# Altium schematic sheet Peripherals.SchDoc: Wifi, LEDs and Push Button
size A4; Author: N.P; CompanyName: STMicroelectronics; Organization: MCD/APPLIS/LMS; DocumentNumber: MB1260; SheetNumber: 11; SheetTotal: 13; Project: STM32F723e-DISCO
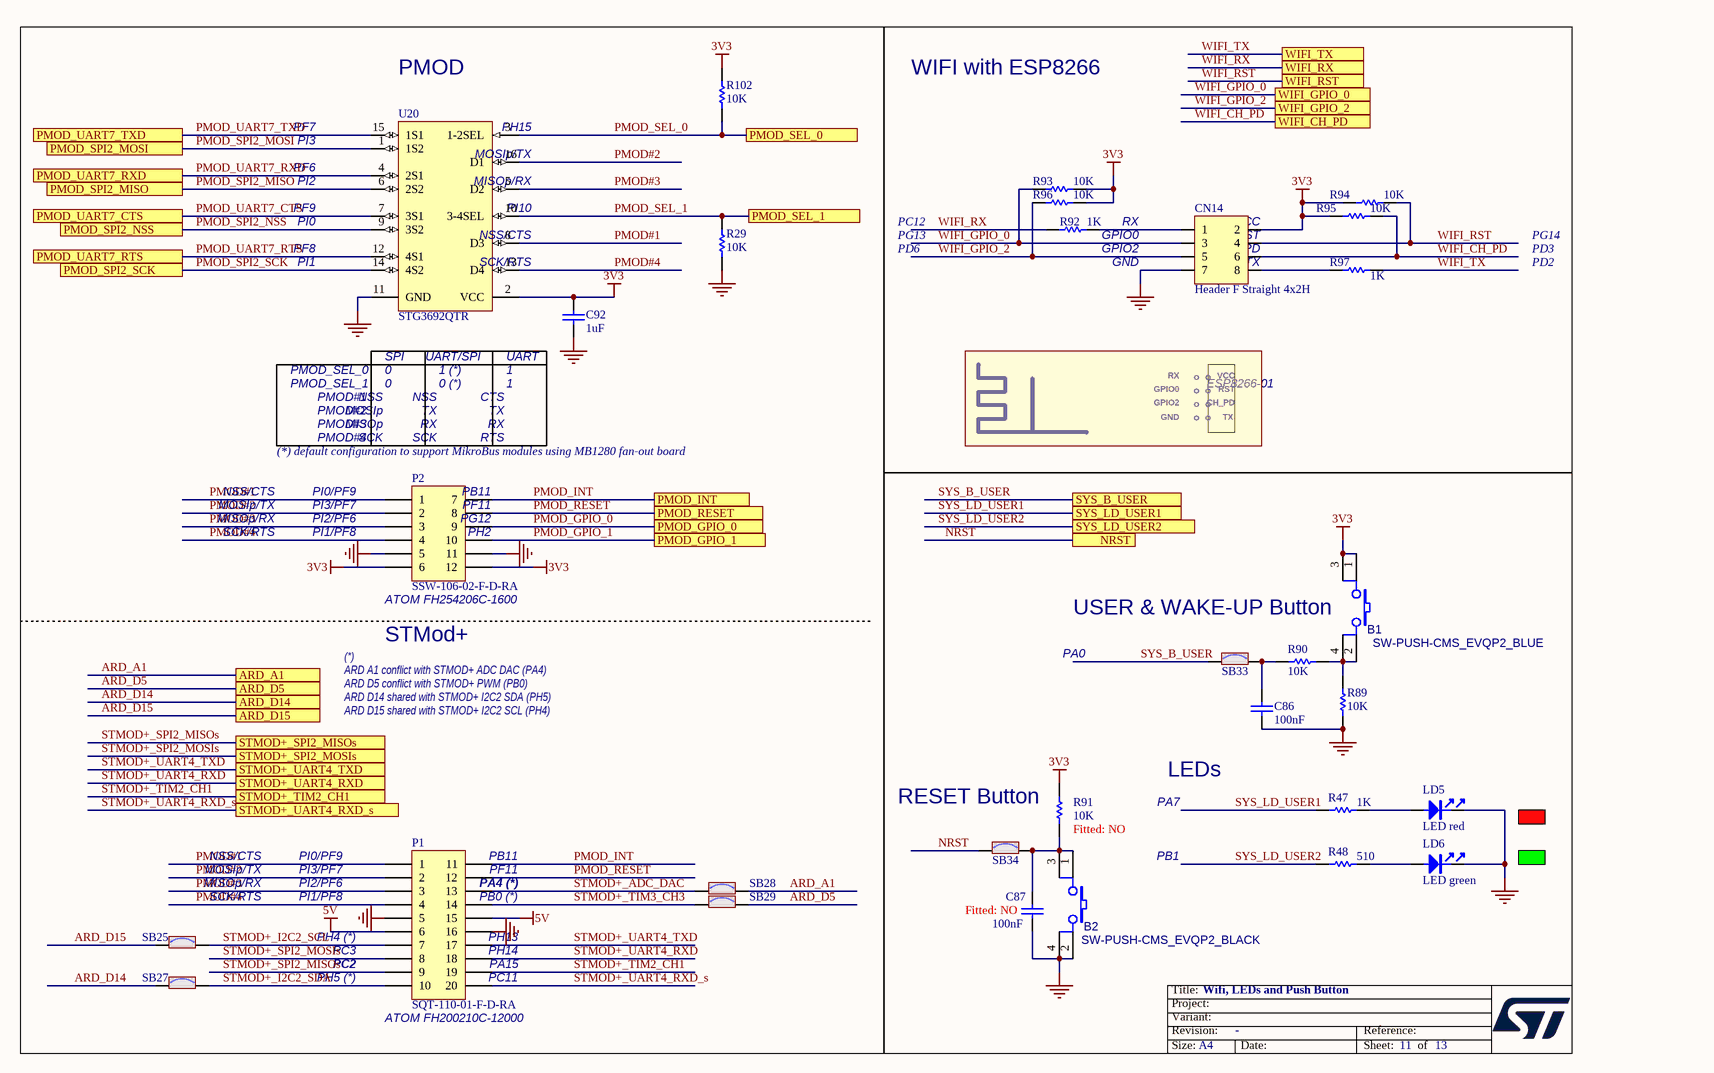
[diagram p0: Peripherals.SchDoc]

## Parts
B1  SW-PUSH-CMS_EVQP2_BLUE  [TACT_4SM_3R5X5R5]
B2  SW-PUSH-CMS_EVQP2_BLACK  [TACT_4SM_3R5X5R5]
C86  100nF  [0402C]
C87  100nF  Fitted: NO  [0402C]
C92  1uF  [0603C]
CN14  Header F Straight 4x2H  [HDR_2X4_2R54]
LD5  LED red  [0603D]
LD6  LED green  [0603D]
P1  SQT-110-01-F-D-RA  [SQT-110-01-F-D-RA]
P2  SSW-106-02-F-D-RA  [SSW-106-02-F-D-RA]
R29  10K  [0402R]
R47  value 1K  [0603R]  (hidden comment: 1K_1%_0603)
R48  value 510  [0603R]  (hidden comment: 510_1%_0603)
R89  10K  [0402R]
R90  10K  [0402R]
R91  Fitted: NO  [0402R]  (hidden comment: 10K)
R92  1K  [0402R]
R93  10K  [0402R]
R94  10K  [0402R]
R95  10K  [0402R]
R96  10K  [0402R]
R97  1K  [0402R]
R102  10K  [0402R]
SB25  Solder Bridge ON  [JP2_SMD]  (value not drawn)
SB27  Solder Bridge ON  [JP2_SMD]  (value not drawn)
SB28  Solder Bridge ON  [JP2_SMD]  (value not drawn)
SB29  Solder Bridge ON  [JP2_SMD]  (value not drawn)
SB33  Solder Bridge ON  [JP2_SMD]  (value not drawn)
SB34  Solder Bridge ON  [JP2_SMD]  (value not drawn)
U20  STG3692QTR  [QFN16_0R4_2R5X1R7]

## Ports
ARD_A1, ARD_D5, ARD_D14, ARD_D15, NRST, PMOD_GPIO_0, PMOD_GPIO_1, PMOD_INT, PMOD_RESET, PMOD_SEL_0, PMOD_SEL_1, PMOD_SPI2_MISO, PMOD_SPI2_MOSI, PMOD_SPI2_NSS, PMOD_SPI2_SCK, PMOD_UART7_CTS, PMOD_UART7_RTS, PMOD_UART7_RXD, PMOD_UART7_TXD, STMOD+_SPI2_MISOs, STMOD+_SPI2_MOSIs, STMOD+_TIM2_CH1, STMOD+_UART4_RXD, STMOD+_UART4_RXD_s, STMOD+_UART4_TXD, SYS_B_USER, SYS_LD_USER1, SYS_LD_USER2, WIFI_CH_PD, WIFI_GPIO_0, WIFI_GPIO_2, WIFI_RST, WIFI_RX, WIFI_TX

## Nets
3V3: B1.1 B1.3 C92.1 CN14.2 P2.6 P2.12 R91.2 R93.1 R94.1 R95.1 R96.1 R102.2 U20.2(VCC)
5V: P1.6 P1.15
GND: B2.2 B2.4 C86.1 C87.1 C92.2 CN14.7 LD5.2 LD6.2 P1.5 P1.16 P2.5 P2.11 R29.1 R89.1 U20.11(GND)
ARD_A1: SB28.2 ; port ARD_A1
ARD_D5: SB29.2 ; port ARD_D5
ARD_D14: SB27.1 ; port ARD_D14
ARD_D15: SB25.1 ; port ARD_D15
NRST: SB34.1 ; port NRST
PMOD#1: P1.1 P2.1 U20.8(D3)
PMOD#2: P1.2 P2.2 U20.16(D1)
PMOD#3: P1.3 P2.3 U20.5(D2)
PMOD#4: P1.4 P2.4 U20.13(D4)
PMOD_GPIO_0: P2.9 ; port PMOD_GPIO_0
PMOD_GPIO_1: P2.10 ; port PMOD_GPIO_1
PMOD_INT: P1.11 P2.7 ; port PMOD_INT
PMOD_RESET: P1.12 P2.8 ; port PMOD_RESET
PMOD_SEL_0: R102.1 U20.3(1-2SEL) ; port PMOD_SEL_0
PMOD_SEL_1: R29.2 U20.10(3-4SEL) ; port PMOD_SEL_1
PMOD_SPI2_MISO: U20.6(2S2) ; port PMOD_SPI2_MISO
PMOD_SPI2_MOSI: U20.1(1S2) ; port PMOD_SPI2_MOSI
PMOD_SPI2_NSS: U20.9(3S2) ; port PMOD_SPI2_NSS
PMOD_SPI2_SCK: U20.14(4S2) ; port PMOD_SPI2_SCK
PMOD_UART7_CTS: U20.7(3S1) ; port PMOD_UART7_CTS
PMOD_UART7_RTS: U20.12(4S1) ; port PMOD_UART7_RTS
PMOD_UART7_RXD: U20.4(2S1) ; port PMOD_UART7_RXD
PMOD_UART7_TXD: U20.15(1S1) ; port PMOD_UART7_TXD
STMOD+_ADC_DAC: P1.13 SB28.1
STMOD+_I2C2_SCL: P1.7 SB25.2
STMOD+_I2C2_SDA: P1.10 SB27.2
STMOD+_SPI2_MISOs: P1.9 ; port STMOD+_SPI2_MISOs
STMOD+_SPI2_MOSIs: P1.8 ; port STMOD+_SPI2_MOSIs
STMOD+_TIM2_CH1: P1.19 ; port STMOD+_TIM2_CH1
STMOD+_TIM3_CH3: P1.14 SB29.1
STMOD+_UART4_RXD: P1.18 ; port STMOD+_UART4_RXD
STMOD+_UART4_RXD_s: P1.20 ; port STMOD+_UART4_RXD_s
STMOD+_UART4_TXD: P1.17 ; port STMOD+_UART4_TXD
SYS_B_USER: SB33.1 ; port SYS_B_USER
SYS_LD_USER1: R47.1 ; port SYS_LD_USER1
SYS_LD_USER2: R48.1 ; port SYS_LD_USER2
WIFI_CH_PD: CN14.6 R95.2 ; port WIFI_CH_PD
WIFI_GPIO_0: CN14.3 R93.2 ; port WIFI_GPIO_0
WIFI_GPIO_2: CN14.5 R96.2 ; port WIFI_GPIO_2
WIFI_RST: CN14.4 R94.2 ; port WIFI_RST
WIFI_RX: R92.1 ; port WIFI_RX
WIFI_TX: R97.2 ; port WIFI_TX
NetB1_2: B1.2 B1.4 R89.2 R90.2
NetB2_1: B2.1 B2.3 C87.2 R91.1 SB34.2
NetC86_2: C86.2 R90.1 SB33.2
NetCN14_1: CN14.1 R92.2
NetCN14_8: CN14.8 R97.1
NetLD5_1: LD5.1 R47.2
NetLD6_1: LD6.1 R48.2

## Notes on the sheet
- PF7
- PMOD
- (near U20) PH15
- WIFI with ESP8266
- PI3
- PF6
- PI2
- (near U20) MOSIp/TX
- (near U20) MISOp/RX
- PF9
- PI1
- PI0
- PF8
- (near U20) PI10
- (near U20) NSS/CTS
- SCK/RTS
- PC12
- PG13
- PD6
- (near CN14) GND
- (near CN14) GPIO2
- (near CN14) GPIO0
- RX
- (near CN14) VCC
- (near CN14) CH_PD
- (near CN14) RST
- (near CN14) TX
- PG14
- PD3
- PD2
- PMOD_SEL_0
- PMOD_SEL_1
- PMOD#1
- 0
- NSS
- SPI
- UART/SPI
- 0 (*)
- 1 (*)
- CTS
- UART
- 1
- GPIO2
- GPIO0
- ° °
- VCC
- CH_PD
- RST
- ESP8266-01
- (near P2) (*) default configuration to support MikroBus modules using MB1280 fan-out board
- PMOD#2
- PMOD#3
- PMOD#4
- MOSIp
- MISOp
- SCK
- TX
- RTS
- GND
- NSS/CTS
- MOSIp/TX
- MISOp/RX
- (near P2) PI0/PF9
- (near P2) PI3/PF7
- (near P2) PI2/PF6
- (near P2) PI1/PF8
- (near P2) PB11
- (near P2) PF11
- (near P2) PG12
- (near P2) PH2
- (near P2) ATOM FH254206C-1600
- STMod+
- USER & WAKE-UP Button
- PA0
- (*)
  ARD A1 conflict with STMOD+ ADC DAC (PA4)
  ARD D5 conflict with STMOD+ PWM (PB0)
  ARD D14 shared with STMOD+ I2C2 SDA (PH5)
  ARD D15 shared with STMOD+ I2C2 SCL (PH4)
- RESET Button
- LEDs
- PA7
- (near P1) PI0/PF9
- (near P1) PI3/PF7
- PB11
- PF11
- PB1
- (near P1) PI2/PF6
- (near P1) PI1/PF8
- (near P1) PH4 (*)
- PA4 (*)
- PB0 (*)
- PH13
- (near P1) PC3
- (near P1) PC2
- (near P1) PH5 (*)
- PH14
- PA15
- PC11
- (near P1) ATOM FH200210C-12000

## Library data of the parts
B1 = SW-PUSH-CMS_EVQP2_BLUE: EVQP2 - 4.7mm x 3.5 mm SMD Light Touch Switch; Manuf_2: Panasonic; Manuf_Part_2: EVQP2B02B; Manuf_Part_1: C-TS-02H-2.5-B-V-T/R; Manuf_1: Jiubaba; Ordered by: Subcon; Fitted: YES
B2 = SW-PUSH-CMS_EVQP2_BLACK: EVQP2 - 4.7mm x 3.5 mm SMD Light Touch Switch; Manuf_2: Panasonic; Manuf_Part_2: EVQP2F02K; Manuf_1: Jiubaba; Manuf_Part_1: C-TS-02H-2.5-K-V-T/R; Ordered by: Subcon; Fitted: YES
C86 = Cap_100nF_X7R_10%_0402: Capacitor,100nF,16V,X7R,10%,0402,YAGEO; Manuf_Part_1: CC0402KRX7R7BB104; Ordered by: Subcon; Fitted: YES
C87 = Cap_100nF_X7R_10%_0402: Capacitor,100nF,16V,X7R,10%,0402,YAGEO; Manuf_Part_1: CC0402KRX7R7BB104; Ordered by: Subcon
C92 = Cap_1uF_X5R_10%_0603: Capacitor,1uF,16V,X5R,10%,0603,YAGEO; Manuf_Part_1: CC0603KRX5R7BB105; Ordered by: Subcon; Fitted: YES
CN14 = Header 4X2F: Header Female, 4-Pin, Dual row, Straight; Manuf_Part_1: BL 2-8G; Manuf_1: Fischer Electronik; Fitted: YES; Ordered by: Subcon
LD5 = LED_red: LED red 0603; Manuf_1: everlight; Manuf_Part_1: 19-213-R6C-AP1Q2B/3T; Ordered by: Subcon; Fitted: YES
LD6 = LED_green: LED green 0603; Manuf_1: everlight; Manuf_Part_1: 19-213SYGC/S530-E2/TR8; Ordered by: Subcon; Fitted: YES
P1 = Header 10X2 TH RA 2mm: 20 Position Receptacle Connector 0.079" (2.00mm) Through Hole Right Angle; Manuf_1: Samtec; Manuf_2: ATOM; Manuf_Part_2: FH200210C-12000; Ordered by: Subcon; Fitted: YES
P2 = Header 6X2 TH RA 2.54mm: 12 Position Receptacle Connector 0.100" (2.54mm) Through Hole Right Angle; Manuf_1: Samtec; Manuf_2: ATOM; Manuf_Part_2: FH254206C-1600; Ordered by: Subcon; Fitted: YES
R29 R89 R90 R93-R96 R102 = Res_10K_1%_0402: Resistor,10K,0402,1%,YAGEO; Manuf_Part_1: RC0402FR-0710KL; Ordered by: Subcon; Fitted: YES
R47 = Res_1K_1%_0603: Resistor,1K,0603,1%,YAGEO; Manuf_Part_1: RC0603FR-071KL; Ordered by: Subcon; Fitted: YES
R48 = Res_510_1%_0603: Resistor,510,0603,1%,YAGEO; Manuf_Part_1: RC0603FR-07510RL; Manuf_Part_2: RT0603FRE07510RL; Ordered by: Subcon; Fitted: YES
R91 = Res_10K_1%_0402: Resistor,10K,0402,1%,YAGEO; Manuf_Part_1: RC0402FR-0710KL; Ordered by: Subcon
R92 R97 = Res_1K_1%_0402: Resistor,1K,0402,1%,YAGEO; Manuf_Part_1: RC0402FR-071KL; Ordered by: Subcon; Fitted: YES
SB25 SB27-SB29 SB33 SB34 = SB_ON: Fitted: YES; Ordered by: Subcon
U20 = STG3692QTR: Low voltage high bandwidth quad SPDT switch; Manuf_1: STM; Fitted: YES; ECCN_US/EU: EAR99/NEC; Ordered by: ST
